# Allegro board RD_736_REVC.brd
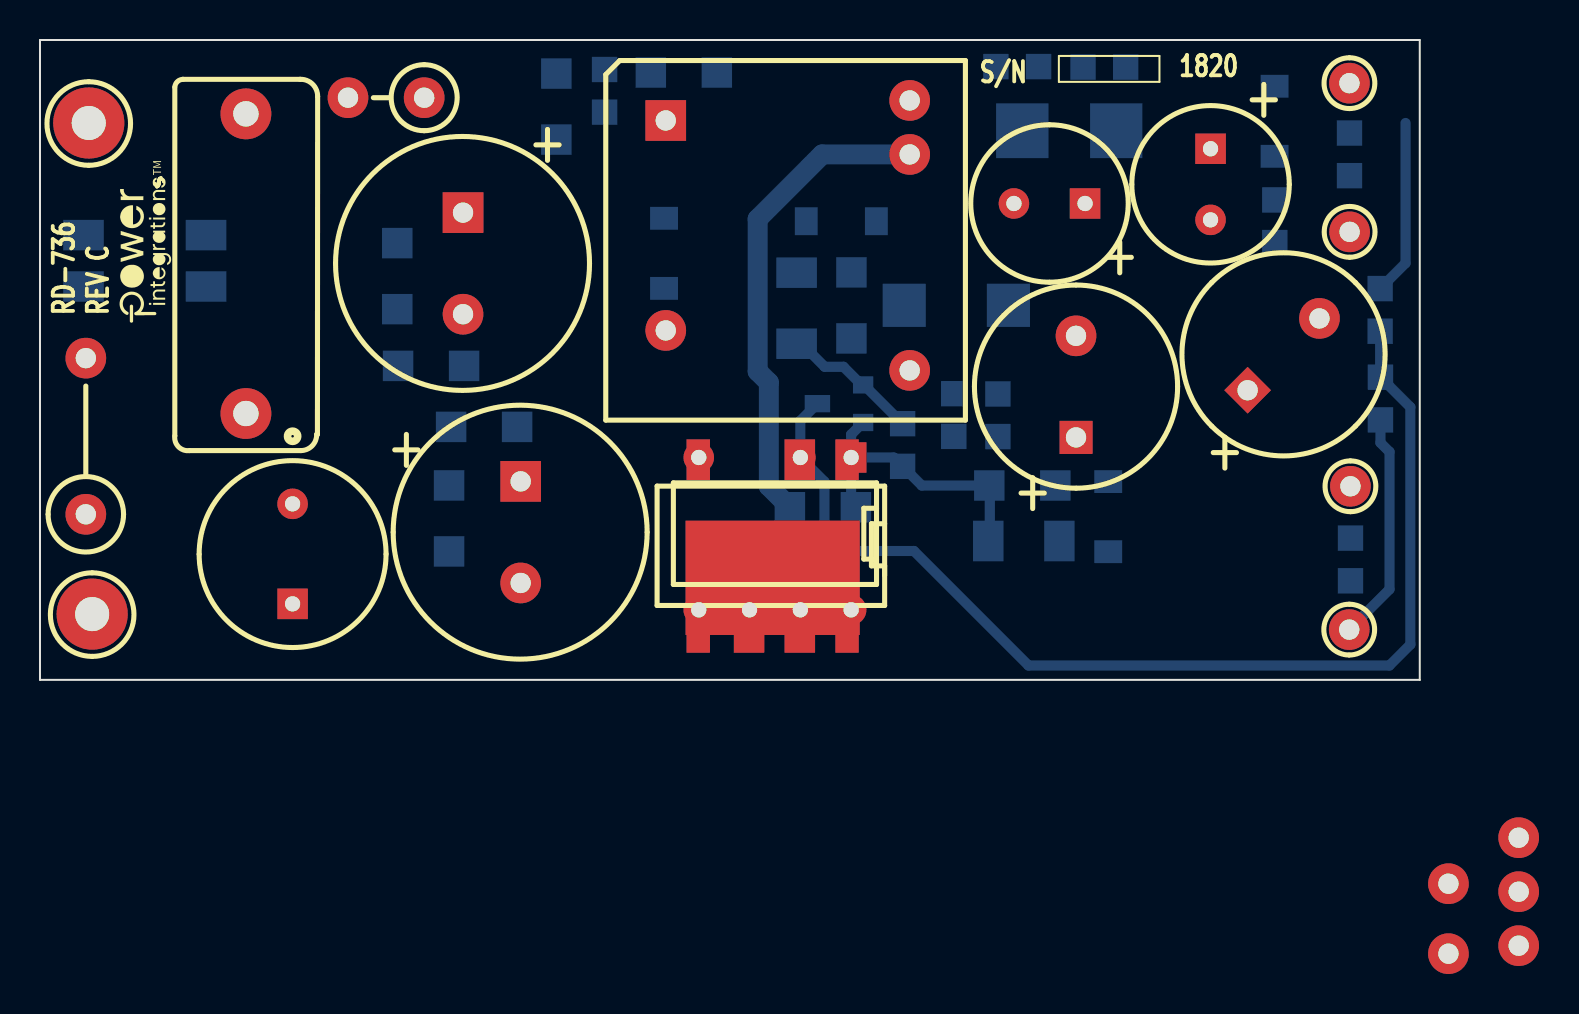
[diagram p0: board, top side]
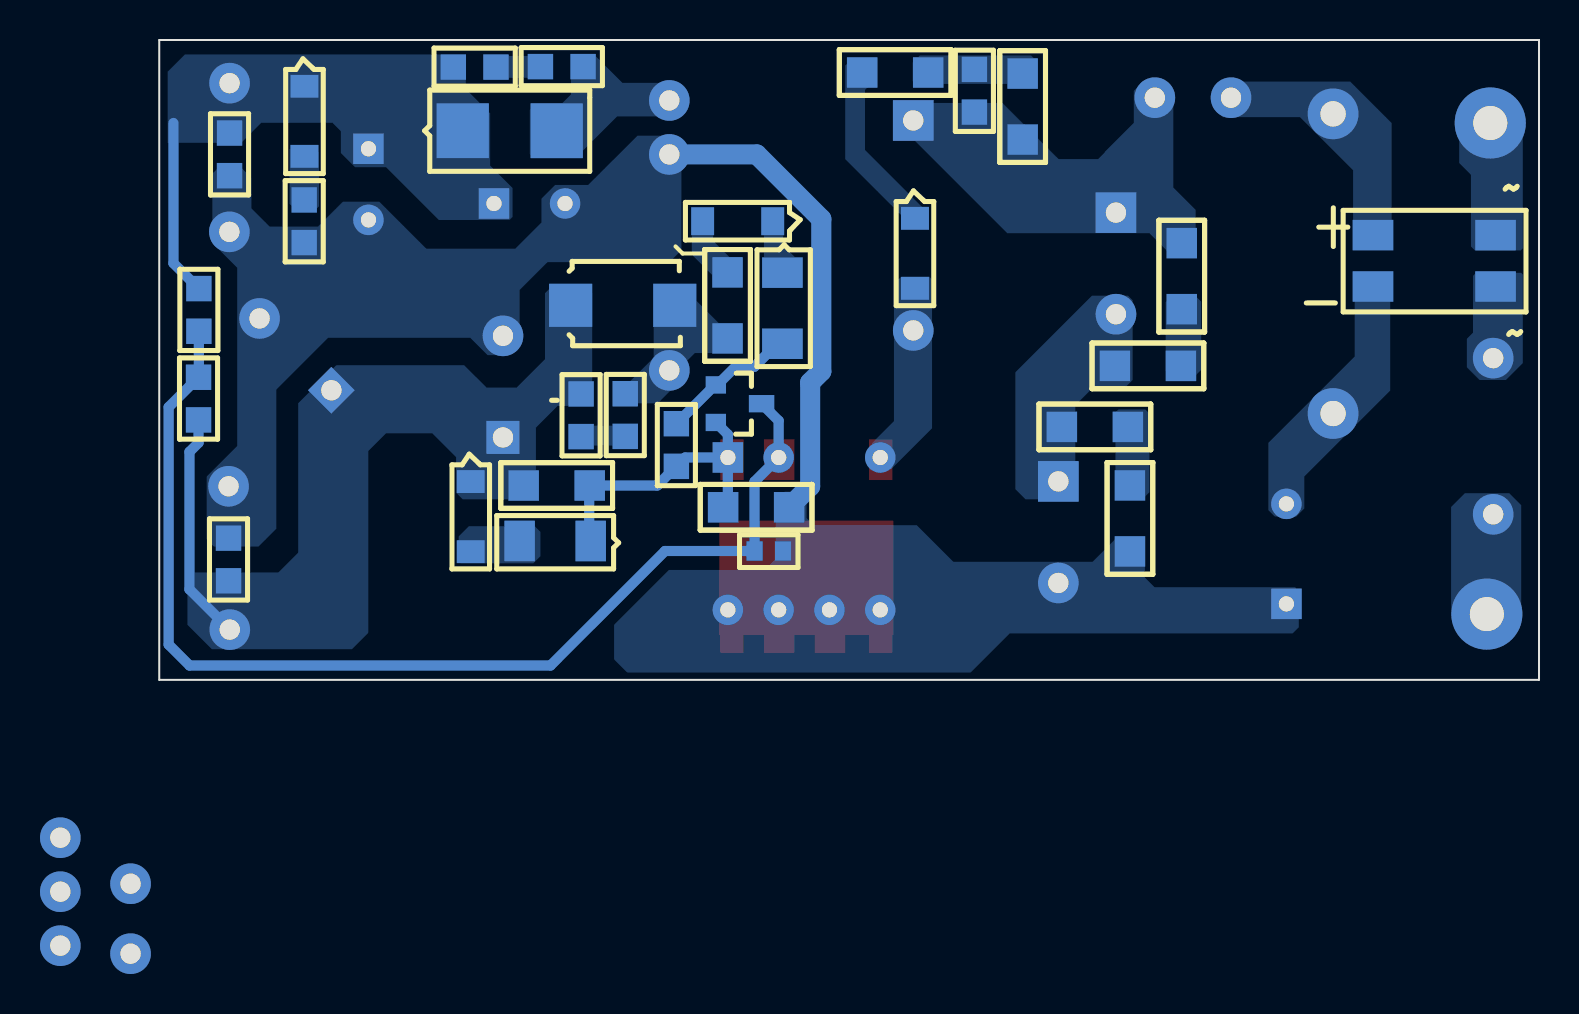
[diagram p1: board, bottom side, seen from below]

Outline 69 x 32 mm; copper layers: TOP, BOTTOM. Coordinates in mm from the lower left corner of the outline.
Outline path: 0,32 0,0 69,0 69,32 0,32

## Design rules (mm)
constraint set DEFAULT: min track width 0.508

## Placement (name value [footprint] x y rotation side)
BR1  B10S-G  [PISMSOIC4]  2.17 19.67 90 bottom
C1  150 nF  [PI_NP_CAPRAD709X276LS590D050]  10.3 28.31 270 top
C2  33 uF  [PIPOLCAPCLYD500LS200040]  21.16 23.37 270 top
C4  100 nF  [PISMC1206]  40.8 8.63 180 bottom
C5  1 nF  [PISMC0805]  47.8 30.67 0 bottom
C6  330 uF  [PIPOLCAPCLYD320LS140030]  58.54 26.56 270 top
C7  330 uF  [PIPOLCAPCLYD320LS140030]  52.26 23.82 180 top
C8  470 uF  [PIPOLCAPCYLD400LS200040]  51.81 12.12 90 top
C9  470 uF  [PIPOLCAPCYLD400LS200040]  60.39 14.48 45 top
C10  1 nF  [PISMC0805]  45.7 14.31 270 bottom
C12  33 uF  [PIPOLCAPCLYD500LS200040]  24.04 9.93 270 top
C13  1 nF  [PISMC0805]  28.24 30.53 270 bottom
D2  FDLL4148  [PISMDMINIMELF]  37.84 20.37 270 bottom
D3  SS26-E3/52T  [PISMDO214AA12]  53.82 27.46 180 bottom
D4  SK3200B-LTP  [PISMSMB]  48.43 18.73 180 bottom
D5  RS1ML  [PI_SM_SOD-123_12]  31.21 23.08 270 bottom
D6  FDLL4148  [PISMDMINIMELF]  47.42 6.94 0 bottom
GND  BLK  [PITPKEYSTONE100X100]  65.53 9.68 0 top
GND`  BLK  [PITPKEYSTONE100X100]  65.49 22.4 0 top
L  WHT  [PITPKEYSTONE125X125]  2.61 3.29 0 top
L1  1000 uH  [PI_CHOKE_RLB9012_D2]  12.63 3.8 90 top
L2  Ferrite Bead (3.5 x 4.45 mm)  [PI12WRESD180LS675D040]  19.21 29.11 180 top
N  BLK  [PITPKEYSTONE125X125]  2.44 27.85 0 top
NOREF  -  []  69 0 90 top
NOREF#2  -  []  -228.6 -151.78 0 top
NOREF#3  -  []  -150.78 47.23 0 top
NOREF#4  -  []  0 32 0 top
NOREF#5  -  []  4.09 17.31 90 top
Q1  PMBTA56  [PISMSOT23123_1]  41.16 12.87 270 bottom
R1  2 k  [PISMR1206]  40.58 20.38 270 bottom
R2  20.0 k  [PISMR1206]  47.47 9.72 0 bottom
R3  2 k  [PISMR0805]  43.14 10.68 90 bottom
R4  16  [PISMR0805]  52.16 30.64 0 bottom
R5  5.11 k  [PISMR0805]  67.02 19.57 270 bottom
R6  2.15 k  [PISMR0603]  39.23 6.44 180 bottom
R7  24.9 k  [PISMR0805]  67.03 15.13 270 bottom
R8  16  [PISMR0805]  47.9 12.17 90 bottom
R13  2 M  [PISMR1206]  17.87 18.54 90 bottom
R14  2 M  [PISMR1206]  21.21 15.7 180 bottom
R15  2 M  [PISMR1206]  20.56 12.65 0 bottom
R16  2 M  [PISMR1206]  20.46 6.42 90 bottom
R20  20  [PISMR1206]  33.85 30.37 180 bottom
R21  200 k  [PISMR1206]  25.82 30.32 270 bottom
R22  4.7 k  [PISMR0805]  61.75 24 270 bottom
R23  1.2 k  [PISMR0805]  65.48 27.35 270 bottom
R24  3.3 k  [PISMR0805]  65.54 7.09 270 bottom
RF1  4.7  [PI_2W_VRESD145LS150D040]  2.29 8.28 90 top
T1  EE16  [PIBOBBINEE1610P4X6]  31.29 27.98 0 top
U1  LNK3696G  [PIICSMD8CSHORT5678]  40.36 11.01 180 top
U2  LNK3696P  [PIICDIP8CSHORT5678]  40.56 11.12 180 top
UNK+5V  RED  [PITPKEYSTONE100X100]  65.48 29.84 0 top
UNK+12V  BLK  [PITPKEYSTONE100X100]  65.47 2.51 0 top
VR1  MMSZ5267BT1G  [PI_SM_SOD-123_12]  38.32 22.94 0 bottom
VR2  MMSZ5242B-7-F  [PI_SM_SOD-123_12]  53.42 9.92 270 bottom
VR3  MMSZ5234B-7-F  [PI_SM_SOD-123_12]  61.74 29.69 270 bottom

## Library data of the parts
BR1 = DIODE BRIDGE_~~+-: alternate symbols: (pi_sm_soic4_slot)
C1 C4 C5 C10 C13 = CAP NP
C2 C12 = CAP POL: alternate symbols: (pipolcapclyd500ls200040800lh)
C6 C7 = CAP POL: alternate symbols: (pipolcapclyd320ls140030430h)
C8 C9 = CAP POL: alternate symbols: (pipolcapclyd400x530ls200030h)
D2 D5 D6 = DIODE
D3 = DIODE SCHOTTKY: alternate symbols: (pismdo214ac12)
D4 = DIODE SCHOTTKY
GND GND` L N UNK+5V UNK+12V = TESTPOINT
L1 = INDUCTOR_DOT2
L2 = INDUCTOR: alternate symbols: (pi12wvresd180ls150d040,pi12wvresd180ls200d040,pi12wvresd180ls250d040)
Q1 = PNP_BEC
R1-R8 R13-R16 R20-R24 = R
RF1 = RF: alternate symbols: (pi_2w_resd145ls455d040)
T1 = BEE16_10P_4x6/GENERIC
U1 = LNK3696_4: alternate symbols: (piicsmd8cshort5678)
U2 = LNK3696_3
VR1-VR3 = DIODE_ZENER

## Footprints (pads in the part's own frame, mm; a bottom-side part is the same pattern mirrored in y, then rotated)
PI12WRESD180LS675D040
  round 2.032 hole 1.016: 1(0,0) 2(3.81,0)
PI_2W_VRESD145LS150D040
  round 2.032 hole 1.016: 1(0,0) 2(7.81,0)
PI_CHOKE_RLB9012_D2
  rect 1.524x1.524 hole 0.762: 1(0,0)
  round 1.524 hole 0.762: 2(5.001,0)
PI_NP_CAPRAD709X276LS590D050
  round 2.54 hole 1.27: 1(0,0) 2(14.986,0)
PI_SM_SOD-123_12
  rect 1.143x1.397 smd: 1(0,0) 2(3.505,0)
PIBOBBINEE1610P4X6
  rect 2.032x2.032 hole 1.016: 1(0,0)
  round 2.032 hole 1.016: 2(39.141,-38.171) 3(39.141,-41.671) 4(0,-10.5) 5(12.2,-12.499) 6(42.654,-41.27) 7(42.654,-38.57) 8(42.654,-35.87) 9(12.2,-1.699) 10(12.2,1.001)
PIICDIP8CSHORT5678
  rect 1.524x1.524 hole 0.762: 1(0,0)
  round 1.524 hole 0.762: 2(2.54,0) 4(7.62,0) 5(7.62,7.62) 6(5.08,7.62) 7(2.54,7.62) 8(0,7.62)
PIICSMD8CSHORT5678
  rect 1.168x2.032 smd: 1(0,0) 4(7.442,0) 5(7.442,8.636) 8(0,8.636)
  rect 1.524x2.032 smd: 2(2.362,0) 6(4.902,8.636) 7(2.362,8.636)
PIPOLCAPCLYD320LS140030
  rect 1.524x1.524 hole 0.762: 1(0,0)
  round 1.524 hole 0.762: 2(3.556,0)
PIPOLCAPCLYD500LS200040
  rect 2.032x2.032 hole 1.016: 1(0,0)
  round 2.032 hole 1.016: 2(5.08,0)
PIPOLCAPCYLD400LS200040
  rect 1.651x1.651 hole 1.016: 1(0,0)
  round 2.032 hole 1.016: 2(5.08,0)
PISMC0805
  rect 1.27x1.27 smd: 1(0,0) 2(2.134,0)
PISMC1206
  rect 1.524x1.524 smd: 1(0,0) 2(3.302,0)
PISMDMINIMELF
  rect 1.524x2.032 smd: 1(0,0) 2(3.556,0)
PISMDO214AA12
  rect 2.616x2.743 smd: 1(0,0) 2(4.699,0)
PISMR0603
  rect 0.813x0.965 smd: 1(0,0) 2(1.422,0)
PISMR0805
  rect 1.27x1.27 smd: 1(0,0) 2(2.134,0)
PISMR1206
  rect 1.524x1.524 smd: 1(0,0) 2(3.302,0)
PISMSMB
  rect 2.159x2.159 smd: 1(0,0) 2(5.207,0)
PISMSOIC4
  rect 1.524x2.032 smd: 1(0,0) 2(2.571,0) 3(2.571,6.129) 4(0,6.129)
PISMSOT23123_1
  rect 0.864x1.016 smd: 1(-1.88,0) 2(0,0)
  rect 0.864x1.27 smd: 3(-0.94,2.286)
PITPKEYSTONE100X100
  round 2.032 hole 1.016: 1(0,0)
PITPKEYSTONE125X125
  round 3.556 hole 1.702: 1(0,0)

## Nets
BP: C4.1 D6.1 Q1.2(EMITTER) R2.1 R3.1 U1.1 U2.1
FB: Q1.3 R5.2 R6.1 R7.1 U1.2 U2.2
POS: C2.1 C13.2 L2.1 R13.2 R21.2 T1.1
SEC WINDING (-): C10.1 D4.2 R1.2 T1.5
SOURCE: C4.2 C6.2 C7.2 C8.2 C9.2 C12.2 GND.1 GND`.1 L1.1 R6.2 R16.1 R22.2 R23.2 R24.1 T1.9 U1.5 U1.6 U1.7 U1.8(S8) U2.5 U2.6 U2.7 U2.8(S8)
N113320: C6.1 C7.1 D3.1 R4.2 R5.1 R23.1 UNK+5V.1 VR3.1
N173843: BR1.3 C1.1 L2.2
N175187: BR1.4 C1.2 L1.2
N1134980: C5.2 R4.1
N2606021: R1.1 VR1.2
N2627623: C5.1 D3.2 T1.10
N2638033: L.1 RF1.1
N2638037: BR1.1 RF1.2
N2638056: BR1.2 N.1
N2642522: C8.1 C9.1 D4.1 R2.2 R7.2 R8.2 R24.2 UNK+12V.1 VR2.1
N2645458: C10.2 R8.1
N2649083: C2.2 C12.1 R14.1 R15.2
N2650921: R13.1 R14.2
N2651642: R15.1 R16.2
N4163745: D5.2 T1.4 U1.4 U2.4
N4175640: D5.1 R20.1
N4176694: C13.1 R20.2 R21.1
N4182640: R22.1 VR3.2
N4208688: D6.2 VR2.2
N4211492: D2.2 Q1.1 R3.2
N4211556: D2.1 VR1.1

Pads without a net: T1 2 3 6 7 8

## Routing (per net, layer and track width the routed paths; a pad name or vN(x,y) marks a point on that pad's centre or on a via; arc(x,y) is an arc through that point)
BP: length 14.9
  BOTTOM w0.508: U2.1 40.56,8.87 C4.1 ; U2.1 42.7,11.12 R3.1 44.1,9.72 R2.1 47.5,9.69 47.5,7.02 D6.1 ; U2.1 40.56,12.27 Q1.2
FB: length 56.6
  BOTTOM w0.508: Q1.3 38.02,12.96 U2.2 39.23,9.91 R6.1 43.71,6.44 49.43,0.72 67.48,0.72 68.53,1.76 68.53,13.64 R7.1 67.02,15.15 R5.2
SOURCE: length 24
  BOTTOM w1: T1.9 39.12,26.28 35.89,23.05 35.89,15.43 36.45,14.87 36.45,9.68 C4.2
N113320: length 8.8
  BOTTOM w0.508: R5.1 68.29,20.84 68.29,27.85
N2642522: length 11.5
  BOTTOM w0.508: R7.2 67.03,11.86 67.49,11.4 67.49,4.53 UNK+12V.1
N4211492: length 7
  BOTTOM w0.508: D2.2 38.09,16.81 39.24,15.66 40.18,15.66 41.09,14.75 Q1.1 41.2,14.75 R3.2

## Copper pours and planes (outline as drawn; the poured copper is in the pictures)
POS on BOTTOM: 31.81,26.95 32.08,27.21 32.08,28.46 31.69,28.85 26.84,28.85 24.03,26.05 22.05,26.05 21.72,26.38 21.72,26.4 20.26,27.86 20.26,29.46 19.76,29.96 18.72,29.96 18.29,29.53 18.29,24.62 17.17,23.51 17.17,21.45 17.37,21.24 18.39,21.24 19.48,22.34 26.59,22.34 31.2,26.95
SEC WINDING (-) on BOTTOM: 42.88,19.7 44.15,19.7 44.27,19.57 44.27,16.11 45.52,14.87 46.13,14.87 46.3,14.69 46.3,13.98 46.15,13.83 44.07,13.83 42.62,15.28 42.62,15.94 42.21,16.34 40.18,16.34 39.93,16.6 39.93,17.43 40.21,17.71 40.89,17.71
SOURCE on TOP (solid shape): 40.99,2.25 32.28,2.25 32.28,7.96 40.99,7.96
SOURCE on BOTTOM: 53.44,17.1 60.55,17.1 63.14,14.51 63.14,7.55 64.03,6.67 66.27,6.67 66.62,7.02 66.62,10.17 65.1,11.69 65.1,20.61 66.34,21.85 66.34,25.31 66.07,25.59 64.87,25.59 64.39,25.11 64.39,23.58 63.47,22.67 61.06,22.67 59.82,23.91 57.99,23.91 55.64,21.56 51.19,21.56 49.89,22.87 49.89,24.06 49.2,24.75 47.55,24.75 45.09,27.21 43.21,27.21 42.89,26.9 42.89,21.49 43.48,20.89 49.58,20.89 50.98,19.49 50.98,16.83 51.28,16.52 51.28,16.49 51.54,16.24 52.58,16.24
SOURCE on BOTTOM: 31.12,7.73 36.27,7.73 36.63,8.09 36.63,9.15 36.88,9.41 37.72,9.41 38.2,8.93 38.18,8.9 38.18,6.03 38.71,5.5 43.51,5.5 46.25,2.75 46.25,1.03 45.59,0.37 28.42,0.37 26.47,2.32 12.32,2.32 12.01,2.63 12.01,4.46 12.19,4.63 19.23,4.63 19.71,5.12 19.71,6.84 20.04,7.17 21.06,7.17 22.33,5.9 29.29,5.9
N113320 on BOTTOM: 52.45,28.33 52.45,25.72 51.33,24.6 51.33,23.15 51.49,23 55.02,23 57.66,25.64 59.21,25.64 59.92,26.35 59.92,27.44 60.34,27.86 63.89,27.86 64.9,26.86 68,26.86 68.07,26.78 68.5,26.78 68.58,26.86 68.58,30.41 67.72,31.28 53.8,31.28 53.67,31.15 53.67,29.55
N173843 on BOTTOM: 7.37,21.55 7.37,27.85 9.44,29.92 15.91,29.92 16.18,29.65 16.18,28.51 15.81,28.14 11.95,28.14 9.3,25.49 9.3,21.83 9.02,21.55
N175187 on BOTTOM: 11.73,10.17 7.44,14.46 7.44,20.25 7.59,20.41 9.09,20.41 9.22,20.28 9.22,16.16 13.54,11.85 13.54,8.49 13.21,8.16 12.14,8.16 11.73,8.57
N1134980 on BOTTOM: 49.68,31.2 52.45,31.2 52.6,31.05 52.6,30.39 52.32,30.11 49.71,30.11 49.48,30.34 49.48,31
N2606021 on BOTTOM: 40.84,19.75 40.31,19.75 40.16,19.9 40.16,20.81 41.3,21.96 41.3,23.45 41.43,23.58 42.27,23.58 42.37,23.48 42.37,21.27
N2627623 on BOTTOM: 48.16,26.12 50.29,26.12 50.47,26.3 50.47,28.51 50.16,28.81 48.87,28.81 48.41,29.27 48.41,31.23 48.37,31.27 47.24,31.27 45.83,29.86 43.33,29.86 42.93,29.45 42.93,28.46 43.21,28.18 46.1,28.18
N2638033 on BOTTOM: 0.89,8.74 0.89,3.54 1.57,2.86 3.66,2.86 4.39,3.59 4.39,8.65 3.71,9.33 1.49,9.33
N2638037 on BOTTOM: 3.3,17.36 3.61,17.05 3.61,15.63 2.97,15 1.65,15 0.81,15.83 0.81,20.28 0.89,20.36 3.15,20.36 3.3,20.2
N2638056 on BOTTOM: 0.91,21.47 0.81,21.57 0.81,28.36 1.91,29.45 3.1,29.45 3.99,28.56 3.99,25.84 3.4,25.26 3.4,21.68 3.2,21.47
N2642522 on BOTTOM: 49.33,19.72 47.73,19.72 47.35,19.34 47.35,14.26 47.9,13.7 49.07,13.7 50.16,12.61 50.16,9.03 53.82,9.03 54.15,9.36 54.15,11.14 55.35,12.33 57.66,12.33 58.55,11.44 58.55,2.35 59.36,1.53 66.37,1.53 67.59,2.75 67.59,5.32 67.54,5.37 63.04,5.37 62.05,6.36 62.05,13.83 60.15,15.73 53.75,15.73 52.63,14.62 51.13,14.62 49.71,16.04 49.71,19.34
N2645458 on BOTTOM: 48.23,12.71 45.31,12.71 45.14,12.53 45.14,11.92 45.34,11.72 48.41,11.72 48.44,11.75 48.44,12.51
N2649083 on BOTTOM: 22.33,14.59 23.19,13.73 23.19,9.33 23.5,9.03 25.68,9.03 26.19,9.54 26.19,15.38 22.35,19.21 20.55,19.21 20.32,18.98 20.32,15 20.73,14.59
N2650921 on BOTTOM: 18.42,19.14 17.12,19.14 16.89,18.91 16.89,15.5 17.27,15.12 18.34,15.12 18.67,15.45 18.67,18.88
N2651642 on BOTTOM: 21.18,13.37 21.18,9.46 20.88,9.15 19.71,9.15 19.48,9.38 19.48,13.32 19.69,13.52 21.03,13.52
N4163745 on BOTTOM: 32.26,19.8 31.89,20.17 30.49,20.17 30.35,20.03 30.35,12.58 32.41,10.53 33.12,10.53 33.36,10.77 33.36,11.83 32.26,12.94
N4175640 on BOTTOM: 33.71,29.5 33.71,26.5 30.76,23.56 30.76,22.92 30.91,22.77 31.42,22.77 34.7,26.05 34.7,30.72 34.37,31.05 33.3,31.05 33.3,29.91
N4176694 on BOTTOM: 31.32,30.87 31.32,29.93 31.19,29.8 25.43,29.8 25.25,29.98 25.25,31.07 25.4,31.23 30.96,31.23
N4182640 on BOTTOM: 62.36,26.65 61.26,26.65 61.01,26.4 61.01,23.68 61.26,23.43 62.1,23.43 62.48,23.81 62.48,26.53
N4208688 on BOTTOM: 50.22,7.68 53.52,7.68 54.03,7.17 54.03,5.93 53.92,5.83 50.29,5.83 49.94,6.18 49.94,7.4
N4211556 on BOTTOM: 37.13,21.07 37.13,19.8 37.24,19.7 38.61,19.7 38.76,19.85 38.76,23.43 38.58,23.61 37.92,23.61 37.8,23.48 37.8,21.73

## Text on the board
Ref Des/Silkscreen Top: S/N | 1820 | RD-736 | REV C
User.6: 14.  FAB HOUSE LOGO,DATE CODE TO BE IN SILK SCREEN ONLY.DO NOT USE COPPER. | 13.  MATERIAL FR4 COPPER 2oz THICKNESS 0.062"
User.8: FIGURE | FINISHED_SIZE | 30.0 | 40.0 | 50.0 | 67.0 | DRILL CHART: TOP to BOTTOM | ALL UNITS ARE IN MILS | PLATED | QTY | 4 | 9 | 26 | 2
